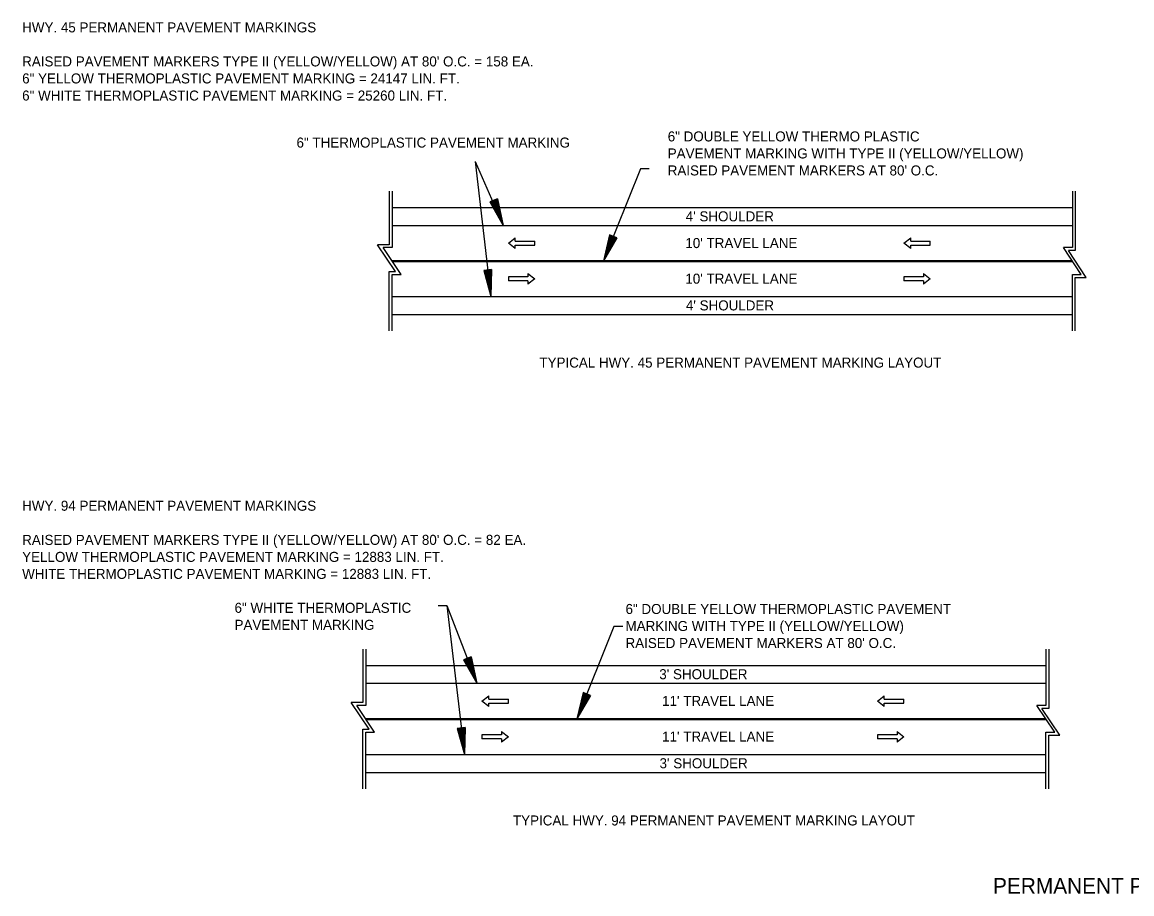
# Model space of a CAD drawing. Extents: x 2261938 to 2263136, y -3124572 to -3124216.
# Drawn here: x 2262807.2 to 2262931.8, y -3124313.5 to -3124215.6 of the extents above; entities that cross this region are included whole.
import ezdxf

# ---------------------------------------------------------------- set-up
doc = ezdxf.new("R2010")
doc.units = 0
for name, color, linetype in [('Default', 7, 'Continuous'), ('R_Draft', 7, 'Continuous'), ('SHET_Border-Text', 7, 'Continuous')]:
    doc.layers.add(name, color=color, linetype=linetype)

msp = doc.modelspace()

# ---------------------------------------------------------------- linework, layer by layer
at = {"layer": 'Default'}
for p, q in [((2262858.02, -3124231.28), (2262861.19, -3124238.45)), ((2262858.02, -3124231.28), (2262859.78, -3124246.45)), ((2262876.59, -3124232.1), (2262872.43, -3124242.45)), ((2262877.59, -3124232.1), (2262876.59, -3124232.1)), ((2262848.37, -3124234.62), (2262848.37, -3124240.62)), ((2262848.71, -3124234.62), (2262848.71, -3124240.95)), ((2262925.1, -3124234.62), (2262925.1, -3124240.95)), ((2262925.43, -3124234.62), (2262925.43, -3124241.29)), ((2262860.53, -3124235.49), (2262859.69, -3124235.81)), ((2262859.69, -3124235.81), (2262861.19, -3124238.45)), ((2262859.76, -3124235.79), (2262861.01, -3124237.99)), ((2262859.83, -3124235.76), (2262860.82, -3124237.5)), ((2262859.9, -3124235.73), (2262860.64, -3124237.04)), ((2262859.97, -3124235.71), (2262860.46, -3124236.56)), ((2262860.04, -3124235.68), (2262860.28, -3124236.1)), ((2262860.18, -3124235.63), (2262860.28, -3124236.1)), ((2262860.25, -3124235.6), (2262860.46, -3124236.56)), ((2262860.32, -3124235.57), (2262860.64, -3124237.04)), ((2262860.39, -3124235.55), (2262860.82, -3124237.5)), ((2262860.46, -3124235.52), (2262861.01, -3124237.99)), ((2262860.53, -3124235.49), (2262861.19, -3124238.45)), ((2262848.71, -3124236.45), (2262925.1, -3124236.45)), ((2262848.71, -3124238.45), (2262925.1, -3124238.45)), ((2262861.76, -3124240.45), (2262862.53, -3124239.85)), ((2262862.53, -3124240.23), (2262862.53, -3124239.85)), ((2262873.13, -3124239.5), (2262872.43, -3124242.45)), ((2262873.96, -3124239.84), (2262872.43, -3124242.45)), ((2262873.2, -3124239.53), (2262872.62, -3124241.99)), ((2262873.89, -3124239.81), (2262872.62, -3124241.99)), ((2262873.27, -3124239.56), (2262872.81, -3124241.51)), ((2262873.82, -3124239.78), (2262872.81, -3124241.51)), ((2262873.34, -3124239.59), (2262872.99, -3124241.05)), ((2262873.75, -3124239.75), (2262872.99, -3124241.05)), ((2262873.96, -3124239.84), (2262873.13, -3124239.5)), ((2262873.41, -3124239.62), (2262873.18, -3124240.57)), ((2262873.68, -3124239.72), (2262873.18, -3124240.57)), ((2262873.48, -3124239.64), (2262873.37, -3124240.11)), ((2262873.61, -3124239.7), (2262873.37, -3124240.11)), ((2262906.17, -3124240.45), (2262906.95, -3124239.85)), ((2262906.95, -3124240.23), (2262906.95, -3124239.85)), ((2262849.08, -3124243.62), (2262847.08, -3124240.62)), ((2262848.37, -3124240.62), (2262847.08, -3124240.62)), ((2262848.71, -3124240.95), (2262847.71, -3124240.95)), ((2262849.71, -3124243.95), (2262847.71, -3124240.95)), ((2262862.53, -3124241.05), (2262861.76, -3124240.45)), ((2262862.53, -3124240.23), (2262864.74, -3124240.23)), ((2262862.53, -3124240.68), (2262864.74, -3124240.68)), ((2262862.53, -3124241.05), (2262862.53, -3124240.68)), ((2262864.74, -3124240.68), (2262864.74, -3124240.23)), ((2262906.95, -3124241.05), (2262906.17, -3124240.45)), ((2262906.95, -3124240.23), (2262909.15, -3124240.23)), ((2262906.95, -3124240.68), (2262909.15, -3124240.68)), ((2262906.95, -3124241.05), (2262906.95, -3124240.68)), ((2262909.15, -3124240.68), (2262909.15, -3124240.23)), ((2262925.1, -3124240.95), (2262924.1, -3124240.95)), ((2262926.1, -3124243.95), (2262924.1, -3124240.95)), ((2262926.65, -3124244.29), (2262924.65, -3124241.29)), ((2262925.43, -3124241.29), (2262924.65, -3124241.29)), ((2262848.74, -3124242.5), (2262925.13, -3124242.5)), ((2262848.37, -3124243.62), (2262849.08, -3124243.62)), ((2262848.37, -3124250.29), (2262848.37, -3124243.62)), ((2262859.88, -3124243.42), (2262858.99, -3124243.53)), ((2262858.99, -3124243.53), (2262859.78, -3124246.45)), ((2262859.06, -3124243.52), (2262859.72, -3124245.96)), ((2262859.14, -3124243.51), (2262859.67, -3124245.44)), ((2262859.21, -3124243.5), (2262859.61, -3124244.95)), ((2262859.29, -3124243.49), (2262859.55, -3124244.44)), ((2262859.37, -3124243.48), (2262859.49, -3124243.94)), ((2262859.51, -3124243.47), (2262859.49, -3124243.94)), ((2262859.58, -3124243.46), (2262859.55, -3124244.44)), ((2262859.66, -3124243.45), (2262859.61, -3124244.95)), ((2262859.73, -3124243.44), (2262859.67, -3124245.44)), ((2262859.81, -3124243.43), (2262859.72, -3124245.96)), ((2262859.88, -3124243.42), (2262859.78, -3124246.45)), ((2262863.96, -3124243.85), (2262863.96, -3124244.23)), ((2262863.96, -3124243.85), (2262864.74, -3124244.45)), ((2262908.38, -3124243.85), (2262908.38, -3124244.23)), ((2262908.38, -3124243.85), (2262909.15, -3124244.45)), ((2262848.71, -3124250.29), (2262848.71, -3124243.95)), ((2262848.71, -3124243.95), (2262849.71, -3124243.95)), ((2262863.96, -3124244.23), (2262861.76, -3124244.23)), ((2262861.76, -3124244.23), (2262861.76, -3124244.68)), ((2262863.96, -3124244.68), (2262861.76, -3124244.68)), ((2262864.74, -3124244.45), (2262863.96, -3124245.05)), ((2262863.96, -3124244.68), (2262863.96, -3124245.05)), ((2262908.38, -3124244.23), (2262906.17, -3124244.23)), ((2262906.17, -3124244.23), (2262906.17, -3124244.68)), ((2262908.38, -3124244.68), (2262906.17, -3124244.68)), ((2262909.15, -3124244.45), (2262908.38, -3124245.05)), ((2262908.38, -3124244.68), (2262908.38, -3124245.05)), ((2262925.1, -3124250.29), (2262925.1, -3124243.95)), ((2262925.1, -3124243.95), (2262926.1, -3124243.95)), ((2262925.43, -3124250.29), (2262925.43, -3124244.29)), ((2262925.43, -3124244.29), (2262926.65, -3124244.29)), ((2262848.71, -3124246.45), (2262925.1, -3124246.45)), ((2262848.71, -3124248.45), (2262925.1, -3124248.45)), ((2262853.87, -3124281.14), (2262854.87, -3124281.14)), ((2262854.87, -3124281.14), (2262858.22, -3124289.86)), ((2262854.87, -3124281.14), (2262856.82, -3124297.86)), ((2262873.62, -3124283.5), (2262869.46, -3124293.86)), ((2262874.62, -3124283.5), (2262873.62, -3124283.5)), ((2262845.41, -3124286.02), (2262845.41, -3124292.02)), ((2262845.74, -3124286.02), (2262845.74, -3124292.36)), ((2262922.13, -3124286.02), (2262922.13, -3124292.36)), ((2262922.46, -3124286.02), (2262922.46, -3124292.69)), ((2262857.57, -3124286.89), (2262856.73, -3124287.22)), ((2262856.73, -3124287.22), (2262858.22, -3124289.86)), ((2262856.8, -3124287.19), (2262858.04, -3124289.39)), ((2262856.87, -3124287.16), (2262857.86, -3124288.91)), ((2262856.94, -3124287.13), (2262857.68, -3124288.44)), ((2262857.01, -3124287.11), (2262857.49, -3124287.97)), ((2262857.08, -3124287.08), (2262857.31, -3124287.5)), ((2262857.21, -3124287.03), (2262857.31, -3124287.5)), ((2262857.28, -3124287), (2262857.49, -3124287.97)), ((2262857.35, -3124286.97), (2262857.68, -3124288.44)), ((2262857.42, -3124286.95), (2262857.86, -3124288.91)), ((2262857.5, -3124286.92), (2262858.04, -3124289.39)), ((2262857.57, -3124286.89), (2262858.22, -3124289.86)), ((2262845.74, -3124287.86), (2262922.13, -3124287.86)), ((2262845.74, -3124289.86), (2262922.13, -3124289.86)), ((2262870.16, -3124290.9), (2262869.46, -3124293.86)), ((2262870.23, -3124290.93), (2262869.65, -3124293.39)), ((2262870.93, -3124291.21), (2262869.65, -3124293.39)), ((2262870.3, -3124290.96), (2262869.84, -3124292.91)), ((2262870.86, -3124291.18), (2262869.84, -3124292.91)), ((2262870.37, -3124290.99), (2262870.03, -3124292.45)), ((2262870.79, -3124291.15), (2262870.03, -3124292.45)), ((2262871, -3124291.24), (2262870.16, -3124290.9)), ((2262870.45, -3124291.02), (2262870.22, -3124291.98)), ((2262870.72, -3124291.13), (2262870.22, -3124291.98)), ((2262870.52, -3124291.05), (2262870.4, -3124291.51)), ((2262870.65, -3124291.1), (2262870.4, -3124291.51)), ((2262846.12, -3124295.02), (2262844.12, -3124292.02)), ((2262845.41, -3124292.02), (2262844.12, -3124292.02)), ((2262845.74, -3124292.36), (2262844.74, -3124292.36)), ((2262846.74, -3124295.36), (2262844.74, -3124292.36)), ((2262858.79, -3124291.86), (2262859.57, -3124291.26)), ((2262859.57, -3124292.46), (2262858.79, -3124291.86)), ((2262859.57, -3124291.63), (2262859.57, -3124291.26)), ((2262859.57, -3124291.63), (2262861.78, -3124291.63)), ((2262859.57, -3124292.08), (2262861.78, -3124292.08)), ((2262859.57, -3124292.46), (2262859.57, -3124292.08)), ((2262861.78, -3124292.08), (2262861.78, -3124291.63)), ((2262871, -3124291.24), (2262869.46, -3124293.86)), ((2262903.2, -3124291.86), (2262903.98, -3124291.26)), ((2262903.98, -3124292.46), (2262903.2, -3124291.86)), ((2262903.98, -3124291.63), (2262903.98, -3124291.26)), ((2262903.98, -3124291.63), (2262906.19, -3124291.63)), ((2262903.98, -3124292.08), (2262906.19, -3124292.08)), ((2262903.98, -3124292.46), (2262903.98, -3124292.08)), ((2262906.19, -3124292.08), (2262906.19, -3124291.63)), ((2262922.13, -3124292.36), (2262921.13, -3124292.36)), ((2262923.13, -3124295.36), (2262921.13, -3124292.36)), ((2262923.69, -3124295.69), (2262921.69, -3124292.69)), ((2262922.46, -3124292.69), (2262921.69, -3124292.69)), ((2262845.71, -3124293.81), (2262922.1, -3124293.81)), ((2262845.77, -3124293.91), (2262922.16, -3124293.91)), ((2262856.92, -3124294.82), (2262856.02, -3124294.93)), ((2262856.02, -3124294.93), (2262856.82, -3124297.86)), ((2262856.1, -3124294.92), (2262856.76, -3124297.36)), ((2262856.17, -3124294.91), (2262856.7, -3124296.85)), ((2262856.25, -3124294.9), (2262856.64, -3124296.35)), ((2262856.32, -3124294.89), (2262856.58, -3124295.84)), ((2262856.4, -3124294.88), (2262856.53, -3124295.35)), ((2262856.54, -3124294.87), (2262856.53, -3124295.35)), ((2262856.62, -3124294.86), (2262856.58, -3124295.84)), ((2262856.69, -3124294.85), (2262856.64, -3124296.35)), ((2262856.77, -3124294.84), (2262856.7, -3124296.85)), ((2262856.84, -3124294.83), (2262856.76, -3124297.36)), ((2262856.92, -3124294.82), (2262856.82, -3124297.86)), ((2262845.41, -3124295.02), (2262846.12, -3124295.02)), ((2262845.41, -3124301.69), (2262845.41, -3124295.02)), ((2262845.74, -3124301.69), (2262845.74, -3124295.36)), ((2262845.74, -3124295.36), (2262846.74, -3124295.36)), ((2262861, -3124295.63), (2262858.79, -3124295.63)), ((2262858.79, -3124295.63), (2262858.79, -3124296.08)), ((2262861, -3124296.08), (2262858.79, -3124296.08)), ((2262861, -3124295.26), (2262861, -3124295.63)), ((2262861, -3124295.26), (2262861.78, -3124295.86)), ((2262861.78, -3124295.86), (2262861, -3124296.46)), ((2262861, -3124296.08), (2262861, -3124296.46)), ((2262905.41, -3124295.63), (2262903.2, -3124295.63)), ((2262903.2, -3124295.63), (2262903.2, -3124296.08)), ((2262905.41, -3124296.08), (2262903.2, -3124296.08)), ((2262905.41, -3124295.26), (2262905.41, -3124295.63)), ((2262905.41, -3124295.26), (2262906.19, -3124295.86)), ((2262906.19, -3124295.86), (2262905.41, -3124296.46)), ((2262905.41, -3124296.08), (2262905.41, -3124296.46)), ((2262922.13, -3124301.69), (2262922.13, -3124295.36)), ((2262922.13, -3124295.36), (2262923.13, -3124295.36)), ((2262922.46, -3124301.69), (2262922.46, -3124295.69)), ((2262922.46, -3124295.69), (2262923.69, -3124295.69)), ((2262845.74, -3124297.86), (2262922.13, -3124297.86)), ((2262845.74, -3124299.86), (2262922.13, -3124299.86))]:
    msp.add_line(p, q, dxfattribs=at)
at = {"layer": 'R_Draft'}
msp.add_line((2262848.67, -3124242.4), (2262925.06, -3124242.4), dxfattribs=at)

# ---------------------------------------------------------------- texts
at = {"layer": 'Default'}
for s, p in [('HWY. 45 PERMANENT PAVEMENT MARKINGS', (2262807.16, -3124216.79)), ("RAISED PAVEMENT MARKERS TYPE II (YELLOW/YELLOW) AT 80' O.C. = 158 EA.", (2262807.16, -3124220.61)), ('6" YELLOW THERMOPLASTIC PAVEMENT MARKING = 24147 LIN. FT.', (2262807.16, -3124222.52)), ('6" WHITE THERMOPLASTIC PAVEMENT MARKING = 25260 LIN. FT.', (2262807.16, -3124224.44)), ('6" THERMOPLASTIC PAVEMENT MARKING', (2262837.97, -3124229.72)), ('6" DOUBLE YELLOW THERMO PLASTIC', (2262879.66, -3124229.03)), ('PAVEMENT MARKING WITH TYPE II (YELLOW/YELLOW)', (2262879.66, -3124230.94)), ("RAISED PAVEMENT MARKERS AT 80' O.C.", (2262879.66, -3124232.85)), ("4' SHOULDER", (2262881.68, -3124238)), ("10' TRAVEL LANE", (2262881.64, -3124241)), ("10' TRAVEL LANE", (2262881.64, -3124245)), ("4' SHOULDER", (2262881.7, -3124248)), ('TYPICAL HWY. 45 PERMANENT PAVEMENT MARKING LAYOUT', (2262865.25, -3124254.42)), ('HWY. 94 PERMANENT PAVEMENT MARKINGS', (2262807.16, -3124270.49)), ("RAISED PAVEMENT MARKERS TYPE II (YELLOW/YELLOW) AT 80' O.C. = 82 EA.", (2262807.16, -3124274.32)), ('YELLOW THERMOPLASTIC PAVEMENT MARKING = 12883 LIN. FT.', (2262807.16, -3124276.23)), ('WHITE THERMOPLASTIC PAVEMENT MARKING = 12883 LIN. FT.', (2262807.16, -3124278.14)), ('6" WHITE THERMOPLASTIC', (2262831.01, -3124281.95)), ('6" DOUBLE YELLOW THERMOPLASTIC PAVEMENT', (2262874.92, -3124282.08)), ('PAVEMENT MARKING', (2262831.01, -3124283.86)), ('MARKING WITH TYPE II (YELLOW/YELLOW)', (2262874.92, -3124283.99)), ("RAISED PAVEMENT MARKERS AT 80' O.C.", (2262874.92, -3124285.9)), ("3' SHOULDER", (2262878.71, -3124289.4)), ("11' TRAVEL LANE", (2262879.03, -3124292.4)), ("11' TRAVEL LANE", (2262879.03, -3124296.4)), ("3' SHOULDER", (2262878.74, -3124299.4)), ('TYPICAL HWY. 94 PERMANENT PAVEMENT MARKING LAYOUT', (2262862.28, -3124305.82))]:
    msp.add_text(s, height=1.125, dxfattribs=at).set_placement(p)
at = {"layer": 'SHET_Border-Text'}
msp.add_text('PERMANENT PAVEMENT MARKING DETAILS', height=1.75, dxfattribs=at).set_placement((2262916.19, -3124313.47))

doc.saveas('drawing.dxf')
